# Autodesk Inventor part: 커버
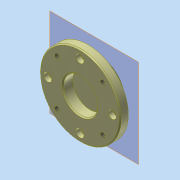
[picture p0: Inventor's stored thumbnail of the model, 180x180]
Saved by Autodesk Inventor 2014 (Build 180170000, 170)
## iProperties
Created: 2023-03
Part Number: 커버
Material: 알루미늄 6061
Document SubType Name: Modeling
Designer: mdu-01
Density: 2.71 g/cm^3
Appearance: 알루미늄 - 평지(1)
Mass: 137.251 g
Surface Area: 162.866 cm^2
Volume: 50.6461 cm^3
Author: mdu-01
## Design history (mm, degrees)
sketch "스케치1"
  geometry: L1 (0, 0)-(0, 20); L2 (0, 20)-(24, 20); L3 (25, 8)-(40, 8); L4 (40, 8)-(40, 1); L5 (39, 0)-(18, 0); L6 (17, 1)-(17, 10); L7 (17, 10)-(0, 10); L8 (40, 1)-(39, 0); L9 (24, 20)-(25, 19); L10 (25, 16.35)-(22.8, 16.35); L11 (22, 15.55)-(22, 12.45); L12 (22.8, 11.65)-(25, 11.65); L13 (22, 14)-(25, 14); L14 (25, 19)-(25, 16.35); L15 (25, 11.65)-(25, 8); L16 (25, 9)-(25, 62) reference; L17 (40, 8)-(40, 70) reference; L18 (18, 0)-(17, 1); A1 r 0.8 centre (22.8, 12.45) between (22, 12.45) and (22.8, 11.65); A2 r 0.8 centre (22.8, 15.55) between (22.8, 16.35) and (22, 15.55); 3 further points
  constraints: 36 end point, 9 perpendicular, 7 parallel, 7 point on line, 4 point on circle, 4 tangent, 3 collinear, 3 vertical, 2 centre point, 2 midpoint, 1 equal radius, 4 other
  dimensions: "d0" = 20 distance of L1.end L1.start; "d1" = 12 distance between parallel lines of L3 L2; "d2" = 34 diameter of L6 L1; "d3" = 10 distance between parallel lines of L5 L7; "d6" = 1 distance of L4.end point (40, 0); "d7" = 1 distance of L5.start point (40, 0) (= d6); "d8" = 1 distance of L2.end point (25, 20) (= d6); "d9" = 1 distance of L9.end point (25, 20) (= d8); "d11" = 6 distance between parallel lines of L13 L2; "d12" = 4.7 distance between parallel lines of L12 L10; "d13" = 44 diameter of L11 L1; "d15" = 0.8 radius of A2; "d17" = 1 distance of L5.end point (17, 0); "d18" = 1 distance of L6.start point (17, 0) (= d17)
revolve "회전1" sketch "스케치1" stored, may be unused: angle "d16" = 90 deg
sketch "스케치2"
  geometry: C1 r 1.621 at (0, 32) reference; C2 r 1.621 at (0, 32) reference; 1 further point
hole "구멍1" sketch "스케치2" at (0, 32) diameter "d19" = 4.5; stored, may be unused: countersink angle "d23" = 82 deg, drill point angle "d25" = 118 deg; dims "d20" = 6, "d21" = 8, "d22" = 4.6, "d24" = 8
sketch "스케치3"
  geometry: C1 r 4 at (0, 32) reference; A1 r 32 centre (0, 0) between (0, 32) and (-22.627, 22.627); 1 further point
  constraints: 2 point on circle, 1 centre point, 1 coincident
  dimensions: "d26" = 45 deg dimension on A1.centre A1.end C1.centre
hole "구멍2" sketch "스케치3" at (-22.627, 22.627) diameter "d27" = 4.917; stored, may be unused: countersink angle "d31" = 82 deg, drill point angle "d33" = 118 deg; dims "d28" = 8, "d29" = 8, "d30" = 4.6, "d32" = 8
node "작업 평면1"
node "솔리드1"
pattern_circular "원형 패턴1" dims angle "d35" = 360 deg
node "참조1"
node "참조2"
